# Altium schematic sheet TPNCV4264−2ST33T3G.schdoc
size 127 x 101 mm
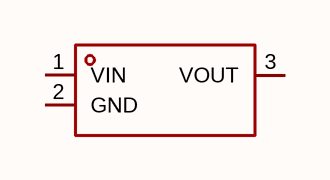
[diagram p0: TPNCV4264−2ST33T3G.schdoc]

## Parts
U?  tpncv4264-2st33t3g  [SOT-223-3_L6.5-W3.4-P2.30-LS7.0-BR-1]  (value not drawn)

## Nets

Not connected (* = marked no-connect by the designer): U? 1(VIN) 2(GND) 3(VOUT)

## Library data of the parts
U? = tpncv4264-2st33t3g: 工作电压:36V;输出电压:3.3V;输出电流:200mA;电源纹波抑制比(PSRR):70dB@(1kHz);; Manufacturer: TECH PUBLIC(台舟); Symbol: TPNCV4264−2ST33T3G; AddInBom: yes; ModelId: 0a360ebfdb9248a182f670f5fd8a68d2; ModelTransform: 275.59,255.905,0,0,0,0,-3.937,0,0; Voltage - Supply: 36V; Output Voltage: 3.3V; Output Current: 200mA; Voltage Dropout: 600mV@(100mA); standby current: 1.5uA; Number of Outputs: 1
